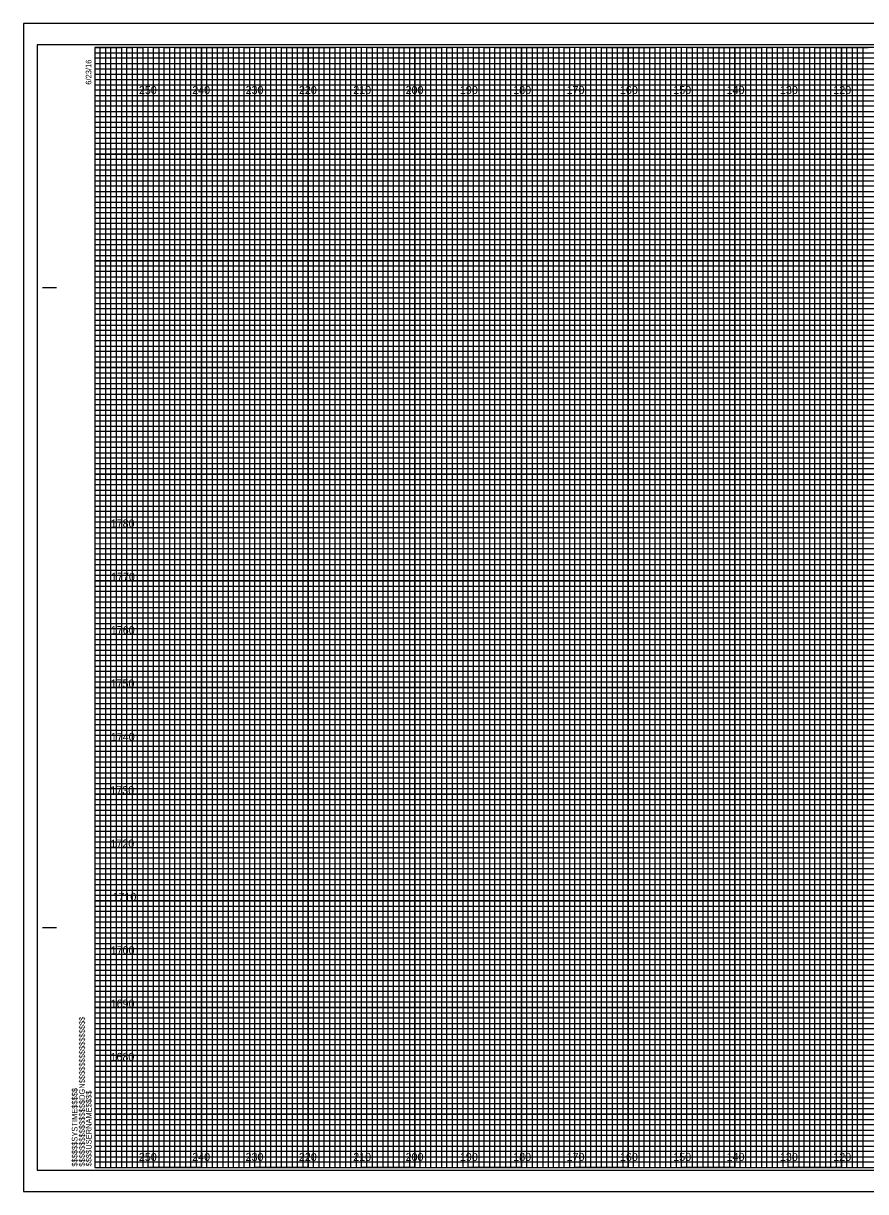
# Model space of a CAD drawing. Extents: x -13 to 1780, y -15 to 3284.
# Drawn here: x 1098.4 to 1256.3, y -11.3 to 207.7 of the extents above; entities that cross this region are included whole.
import ezdxf

# ---------------------------------------------------------------- set-up
doc = ezdxf.new("R2010")
doc.units = 0
for name, color, linetype in [('Prop Retaining Wall', 7, 'Continuous'), ('Prop SS Cut Line', 7, 'Continuous'), ('Prop SS Fill Line', 7, 'Continuous'), ('Prop SS Transition Line', 7, 'Continuous'), ('Prop XS Earthwork Shape', 7, 'Continuous'), ('Prop XS Noise Wall', 7, 'Continuous'), ('Prop XS Station Labels', 7, 'Continuous'), ('Raster_Level_0', 7, 'Continuous'), ('Scratch_Level_3', 7, 'Continuous'), ('Scratch_Level_7', 7, 'Continuous'), ('Typical Bridge Rail CELL', 7, 'Continuous')]:
    doc.layers.add(name, color=color, linetype=linetype)

msp = doc.modelspace()

# ---------------------------------------------------------------- linework, layer by layer
at = {"layer": 'Prop Retaining Wall'}
for p, q in [((1101.99, 158.2), (1104.49, 158.2)), ((1102.09, 158.2), (1104.59, 158.2)), ((1101.99, 38.2), (1104.49, 38.2)), ((1102.09, 38.2), (1104.59, 38.2)), ((1111.79, -6.8), (1111.79, -6.8)), ((1111.79, -6.8), (1111.79, -6.8)), ((1111.79, -6.8), (1111.79, -6.8)), ((1111.79, -6.8), (1111.79, -6.8)), ((1111.79, -6.8), (1111.79, -6.8)), ((1111.79, -6.8), (1111.79, -6.8)), ((1111.79, -6.8), (1111.79, -6.8))]:
    msp.add_line(p, q, dxfattribs=at)
msp.add_lwpolyline([(1431.79, 203.2), (1111.79, 203.2), (1111.79, -6.8), (1431.79, -6.8)], close=True, dxfattribs=at)
at = {"layer": 'Prop SS Cut Line'}
for points in [[(1111.79, 203.2), (1116.79, 203.2), (1116.79, -6.8), (1126.79, -6.8), (1126.79, 203.2), (1136.79, 203.2), (1136.79, -6.8), (1146.79, -6.8), (1146.79, 203.2), (1156.79, 203.2), (1156.79, -6.8), (1166.79, -6.8), (1166.79, 203.2), (1176.79, 203.2), (1176.79, -6.8), (1186.79, -6.8), (1186.79, 203.2), (1196.79, 203.2), (1196.79, -6.8), (1206.79, -6.8), (1206.79, 203.2), (1216.79, 203.2), (1216.79, -6.8), (1226.79, -6.8), (1226.79, 203.2), (1236.79, 203.2), (1236.79, -6.8), (1246.79, -6.8), (1246.79, 203.2), (1256.79, 203.2)], [(1111.79, 198.2), (1386.79, 198.2)], [(1111.79, 178.2), (1431.79, 178.2), (1431.79, 188.2), (1111.79, 188.2)], [(1111.79, 158.2), (1431.79, 158.2), (1431.79, 168.2), (1111.79, 168.2)], [(1111.79, 138.2), (1431.79, 138.2), (1431.79, 148.2), (1111.79, 148.2)], [(1111.79, 118.2), (1431.79, 118.2), (1431.79, 128.2), (1111.79, 128.2)], [(1111.79, 98.2), (1431.79, 98.2), (1431.79, 108.2), (1111.79, 108.2)], [(1111.79, 78.2), (1431.79, 78.2), (1431.79, 88.2), (1111.79, 88.2)], [(1111.79, 58.2), (1431.79, 58.2), (1431.79, 68.2), (1111.79, 68.2)], [(1111.79, 38.2), (1431.79, 38.2), (1431.79, 48.2), (1111.79, 48.2)], [(1111.79, 18.2), (1431.79, 18.2), (1431.79, 28.2), (1111.79, 28.2)], [(1111.79, -1.8), (1431.79, -1.8), (1431.79, 8.2), (1111.79, 8.2)]]:
    msp.add_lwpolyline(points, dxfattribs=at)
at = {"layer": 'Prop SS Fill Line'}
for p, q in [((1121.79, 203.2), (1111.79, 203.2)), ((1121.79, -6.8), (1121.79, 203.2)), ((1141.79, 203.2), (1131.79, 203.2)), ((1131.79, 203.2), (1131.79, -6.8)), ((1141.79, -6.8), (1141.79, 203.2)), ((1161.79, 203.2), (1151.79, 203.2)), ((1151.79, 203.2), (1151.79, -6.8)), ((1161.79, -6.8), (1161.79, 203.2)), ((1181.79, 203.2), (1171.79, 203.2)), ((1171.79, 203.2), (1171.79, -6.8)), ((1181.79, -6.8), (1181.79, 203.2)), ((1201.79, 203.2), (1191.79, 203.2)), ((1191.79, 203.2), (1191.79, -6.8)), ((1201.79, -6.8), (1201.79, 203.2)), ((1221.79, 203.2), (1211.79, 203.2)), ((1211.79, 203.2), (1211.79, -6.8)), ((1221.79, -6.8), (1221.79, 203.2)), ((1241.79, 203.2), (1231.79, 203.2)), ((1231.79, 203.2), (1231.79, -6.8)), ((1241.79, -6.8), (1241.79, 203.2)), ((1261.79, 203.2), (1251.79, 203.2)), ((1251.79, 203.2), (1251.79, -6.8)), ((1131.79, -6.8), (1121.79, -6.8)), ((1151.79, -6.8), (1141.79, -6.8)), ((1171.79, -6.8), (1161.79, -6.8)), ((1191.79, -6.8), (1181.79, -6.8)), ((1211.79, -6.8), (1201.79, -6.8)), ((1231.79, -6.8), (1221.79, -6.8)), ((1251.79, -6.8), (1241.79, -6.8))]:
    msp.add_line(p, q, dxfattribs=at)
for points in [[(1111.79, 193.2), (1431.79, 193.2), (1431.79, 183.2), (1111.79, 183.2)], [(1111.79, 173.2), (1431.79, 173.2), (1431.79, 163.2), (1111.79, 163.2)], [(1111.79, 153.2), (1431.79, 153.2), (1431.79, 143.2), (1111.79, 143.2)], [(1111.79, 133.2), (1431.79, 133.2), (1431.79, 123.2), (1111.79, 123.2)], [(1111.79, 113.2), (1431.79, 113.2), (1431.79, 103.2), (1111.79, 103.2)], [(1111.79, 93.2), (1431.79, 93.2), (1431.79, 83.2), (1111.79, 83.2)], [(1111.79, 73.2), (1431.79, 73.2), (1431.79, 63.2), (1111.79, 63.2)], [(1111.79, 53.2), (1431.79, 53.2), (1431.79, 43.2), (1111.79, 43.2)], [(1111.79, 33.2), (1431.79, 33.2), (1431.79, 23.2), (1111.79, 23.2)], [(1111.79, 13.2), (1431.79, 13.2), (1431.79, 3.2), (1111.79, 3.2)]]:
    msp.add_lwpolyline(points, dxfattribs=at)
at = {"layer": 'Prop SS Transition Line'}
for p, q in [((1111.79, 202.2), (1371.79, 202.2)), ((1371.79, 201.18), (1111.79, 201.18)), ((1111.79, 201.18), (1111.79, 200.2)), ((1111.79, 200.2), (1371.79, 200.2)), ((1371.79, 199.09), (1111.79, 199.09)), ((1111.79, 199.09), (1111.79, 197.2)), ((1111.79, 197.2), (1431.79, 197.2))]:
    msp.add_line(p, q, dxfattribs=at)
for points in [[(1111.79, 196.2), (1381.79, 196.2), (1431.79, 196.2), (1431.79, 195.2), (1111.79, 195.2)], [(1111.79, 194.2), (1431.79, 194.2), (1431.79, 192.2), (1111.79, 192.2)], [(1111.79, 191.2), (1431.79, 191.2), (1431.79, 190.2), (1111.79, 190.18)], [(1111.79, 189.2), (1431.79, 189.2), (1431.79, 187.2), (1111.79, 187.2)], [(1111.79, 186.2), (1431.79, 186.2), (1431.79, 185.2), (1111.79, 185.2)], [(1111.79, 184.2), (1431.79, 184.2), (1431.79, 182.2), (1111.79, 182.2)], [(1111.79, 181.2), (1431.79, 181.2), (1431.79, 180.2), (1111.79, 180.2)], [(1111.79, 179.2), (1431.79, 179.2), (1431.79, 177.2), (1111.79, 177.2)], [(1111.79, 176.2), (1431.79, 176.2), (1431.79, 175.2), (1111.79, 175.2)], [(1111.79, 174.2), (1431.79, 174.2), (1431.79, 172.2), (1111.79, 172.2)], [(1111.79, 171.2), (1431.79, 171.2), (1431.79, 170.2), (1111.79, 170.2)], [(1111.79, 169.2), (1431.79, 169.2), (1431.79, 167.15), (1431.79, 166.2), (1431.79, 165.2), (1111.79, 165.2)], [(1111.79, 167.2), (1431.79, 167.2), (1431.79, 166.2), (1111.79, 166.2)], [(1111.79, 164.2), (1431.79, 164.2), (1431.79, 162.2), (1111.79, 162.23)], [(1111.79, 162.23), (1431.79, 162.2), (1431.79, 161.2), (1111.79, 161.2)], [(1111.79, 160.2), (1431.79, 160.2), (1431.79, 159.2), (1111.79, 159.2)], [(1111.79, 157.2), (1431.79, 157.2), (1431.79, 156.2), (1111.79, 156.2)], [(1111.79, 155.2), (1431.79, 155.2), (1431.79, 154.2), (1111.79, 154.2)], [(1111.72, 152.09), (1431.79, 152.09), (1431.79, 151.08), (1111.72, 151.08)], [(1111.79, 150.2), (1431.79, 150.2), (1431.79, 149.2), (1111.79, 149.2)], [(1111.79, 147.2), (1431.79, 147.2), (1431.79, 146.2), (1111.79, 146.2)], [(1111.79, 145.2), (1431.79, 145.2), (1431.79, 144.2), (1111.79, 144.2)], [(1111.79, 142.2), (1431.79, 142.2), (1431.79, 141.2), (1111.79, 141.2)], [(1111.79, 140.2), (1431.79, 140.2), (1431.79, 139.2), (1111.79, 139.2)], [(1111.79, 137.2), (1431.79, 137.2), (1431.79, 136.2), (1111.79, 136.2)], [(1111.79, 135.2), (1431.79, 135.2), (1431.79, 134.2), (1111.79, 134.2)], [(1111.79, 132.2), (1431.79, 132.2), (1431.78, 131.18), (1111.79, 131.2)], [(1111.79, 130.2), (1431.79, 130.2), (1431.79, 129.2), (1111.79, 129.2)], [(1111.79, 127.2), (1431.79, 127.2), (1431.79, 126.2), (1111.79, 126.2)], [(1111.79, 125.2), (1431.79, 125.2), (1431.79, 124.2), (1111.79, 124.2)], [(1111.79, 122.2), (1431.79, 122.2), (1431.79, 121.2), (1111.79, 121.2)], [(1111.79, 120.2), (1431.79, 120.2), (1431.79, 119.2), (1111.79, 119.2)], [(1111.79, 117.2), (1431.79, 117.2), (1431.79, 116.2), (1111.79, 116.2)], [(1111.79, 115.2), (1431.79, 115.2), (1431.79, 114.2), (1111.79, 114.2)], [(1111.79, 112.2), (1431.79, 112.2), (1431.79, 111.2), (1111.79, 111.2)], [(1111.79, 110.19), (1431.86, 110.11), (1431.79, 109.2), (1111.79, 109.2)], [(1111.79, 107.2), (1431.79, 107.2), (1431.79, 106.2), (1111.79, 106.2)], [(1111.79, 105.2), (1431.79, 105.2), (1431.79, 104.2), (1111.79, 104.2)], [(1111.79, 102.2), (1431.79, 102.2), (1431.79, 101.2), (1111.79, 101.2)], [(1111.79, 100.2), (1431.79, 100.2), (1431.79, 99.2), (1111.79, 99.2)], [(1111.79, 97.2), (1431.79, 97.2), (1431.79, 96.2), (1111.79, 96.2)], [(1111.79, 95.2), (1431.79, 95.2), (1431.79, 94.2), (1111.79, 94.2)], [(1111.79, 92.2), (1431.79, 92.2), (1431.79, 91.2), (1111.79, 91.2)], [(1111.79, 90.2), (1431.79, 90.2), (1431.79, 89.2), (1111.79, 89.2)], [(1111.79, 87.2), (1431.79, 87.2), (1431.79, 86.2), (1111.79, 86.2)], [(1111.79, 85.2), (1431.79, 85.2), (1431.79, 84.2), (1111.79, 84.2)], [(1111.79, 82.2), (1431.79, 82.2), (1431.79, 81.2), (1111.79, 81.2)], [(1111.79, 80.2), (1431.79, 80.2), (1431.79, 79.2), (1111.79, 79.2)], [(1111.79, 77.2), (1431.79, 77.2), (1431.79, 76.2), (1111.79, 76.2)], [(1111.79, 75.2), (1431.79, 75.2), (1431.79, 74.2), (1111.79, 74.2)], [(1111.79, 72.2), (1431.79, 72.2), (1431.78, 71.18), (1111.79, 71.2)], [(1111.79, 70.2), (1431.79, 70.2), (1431.79, 69.2), (1111.79, 69.2)], [(1111.79, 67.2), (1431.79, 67.2), (1431.79, 66.2), (1111.79, 66.2)], [(1111.79, 65.2), (1431.79, 65.2), (1431.79, 64.2), (1111.79, 64.2)], [(1111.79, 62.2), (1431.79, 62.2), (1431.79, 61.2), (1111.79, 61.2)], [(1111.79, 60.2), (1431.79, 60.2), (1431.79, 59.2), (1111.79, 59.2)], [(1111.79, 57.2), (1431.79, 57.2), (1431.79, 56.2), (1111.79, 56.2)], [(1111.79, 55.2), (1431.79, 55.2), (1431.79, 54.2), (1111.79, 54.2)], [(1111.79, 52.2), (1431.79, 52.2), (1431.79, 51.2), (1111.79, 51.2)], [(1111.79, 50.19), (1431.86, 50.11), (1431.79, 49.2), (1111.79, 49.2)], [(1111.79, 47.2), (1431.79, 47.2), (1431.79, 46.2), (1111.79, 46.2)], [(1111.79, 45.2), (1431.79, 45.2), (1431.79, 44.2), (1111.79, 44.2)], [(1111.79, 42.2), (1431.79, 42.2), (1431.79, 41.2), (1111.79, 41.2)], [(1111.79, 40.2), (1431.79, 40.2), (1431.79, 39.2), (1111.79, 39.2)], [(1111.79, 37.2), (1431.79, 37.2), (1431.79, 36.2), (1111.79, 36.2)], [(1111.79, 35.2), (1431.79, 35.2), (1431.79, 34.2), (1111.79, 34.2)], [(1111.79, 32.2), (1431.79, 32.2), (1431.79, 31.2), (1111.79, 31.2)], [(1111.79, 30.2), (1431.79, 30.2), (1431.79, 29.2), (1111.79, 29.2)], [(1111.79, 27.2), (1431.79, 27.2), (1431.79, 26.2), (1111.79, 26.2)], [(1111.79, 25.2), (1431.79, 25.2), (1431.79, 24.2), (1111.79, 24.2)], [(1111.79, 22.2), (1431.79, 22.2), (1431.79, 21.2), (1111.79, 21.2)], [(1111.79, 20.2), (1431.79, 20.2), (1431.79, 19.2), (1111.79, 19.2)], [(1111.79, 17.2), (1431.79, 17.2), (1431.79, 16.2), (1111.79, 16.2)], [(1111.79, 15.2), (1431.79, 15.2), (1431.79, 14.2), (1111.79, 14.2)], [(1111.79, 12.2), (1431.79, 12.2), (1431.79, 11.2), (1111.79, 11.2)], [(1111.79, 10.2), (1431.79, 10.2), (1431.79, 9.2), (1111.79, 9.2)], [(1111.79, 7.2), (1431.79, 7.2), (1431.79, 6.2), (1111.79, 6.2)], [(1111.79, 5.2), (1431.79, 5.2), (1431.79, 4.2), (1111.79, 4.2)], [(1111.79, 2.2), (1431.79, 2.2), (1431.79, 1.2), (1111.79, 1.2)], [(1111.79, 0.2), (1431.79, 0.2), (1431.79, -0.8), (1111.79, -0.8)], [(1111.79, -2.8), (1431.79, -2.8), (1431.79, -3.8), (1111.79, -3.8)], [(1111.79, -4.8), (1431.79, -4.8), (1431.79, -5.8), (1111.79, -5.8)]]:
    msp.add_lwpolyline(points, dxfattribs=at)
at = {"layer": 'Prop XS Earthwork Shape'}
msp.add_lwpolyline([(1098.39, -11.3), (1435.09, -11.3), (1435.09, 207.7), (1098.39, 207.7)], close=True, dxfattribs=at)
at = {"layer": 'Prop XS Noise Wall'}
for p, q in [((1121.79, -6.8), (1121.79, 203.2)), ((1131.79, -6.8), (1131.79, 203.2)), ((1141.79, -6.8), (1141.79, 203.2)), ((1151.79, -6.8), (1151.79, 203.2)), ((1161.79, -6.8), (1161.79, 203.2)), ((1171.79, -6.8), (1171.79, 203.2)), ((1181.79, -6.8), (1181.79, 203.2)), ((1191.79, -6.8), (1191.79, 203.2)), ((1201.79, -6.8), (1201.79, 203.2)), ((1211.79, -6.8), (1211.79, 203.2)), ((1221.79, -6.8), (1221.79, 203.2)), ((1231.79, -6.8), (1231.79, 203.2)), ((1241.79, -6.8), (1241.79, 203.2)), ((1251.79, -6.8), (1251.79, 203.2)), ((1111.79, 193.2), (1431.79, 193.2)), ((1111.79, 183.2), (1431.79, 183.2)), ((1111.79, 173.2), (1431.79, 173.2)), ((1111.79, 163.2), (1431.79, 163.2)), ((1111.79, 153.2), (1431.79, 153.2)), ((1111.79, 143.2), (1431.79, 143.2)), ((1111.79, 133.2), (1431.79, 133.2)), ((1111.79, 123.2), (1431.79, 123.2)), ((1111.79, 113.2), (1431.79, 113.2)), ((1111.79, 103.2), (1431.79, 103.2)), ((1111.79, 93.2), (1431.79, 93.2)), ((1111.79, 83.2), (1431.79, 83.2)), ((1111.79, 73.2), (1431.79, 73.2)), ((1111.79, 63.2), (1431.79, 63.2)), ((1111.79, 53.2), (1431.79, 53.2)), ((1111.79, 43.2), (1431.79, 43.2)), ((1111.79, 33.2), (1431.79, 33.2)), ((1111.79, 23.2), (1431.79, 23.2)), ((1111.79, 13.2), (1431.79, 13.2)), ((1111.79, 3.2), (1431.79, 3.2))]:
    msp.add_line(p, q, dxfattribs=at)
at = {"layer": 'Prop XS Station Labels'}
for p, q in [((1435.09, 207.7), (1098.39, 207.7)), ((1098.39, 207.7), (1098.39, -11.3)), ((1098.39, -11.3), (1435.09, -11.3))]:
    msp.add_line(p, q, dxfattribs=at)
at = {"layer": 'Scratch_Level_7'}
msp.add_lwpolyline([(1100.99, -7.3), (1434.19, -7.3), (1434.19, 203.7), (1100.99, 203.7)], close=True, dxfattribs=at)
at = {"layer": 'Typical Bridge Rail CELL'}
for points in [[(1111.79, -6.8), (1112.79, -6.8), (1112.79, 203.2), (1113.79, 203.2), (1113.79, -6.8)], [(1113.79, -6.8), (1114.79, -6.8), (1114.79, 203.2), (1115.79, 203.2), (1115.79, -6.8)], [(1116.79, -6.8), (1117.79, -6.8), (1117.79, 203.2), (1118.79, 203.2), (1118.79, -6.8)], [(1118.79, -6.8), (1119.79, -6.8), (1119.79, 203.2), (1120.79, 203.2), (1120.79, -6.8)], [(1121.79, -6.8), (1122.79, -6.8), (1122.79, 203.2), (1123.79, 203.2), (1123.79, -6.8)], [(1123.79, -6.8), (1124.79, -6.8), (1124.79, 203.2), (1125.79, 203.2), (1125.79, -6.8)], [(1126.79, -6.8), (1127.79, -6.8), (1127.79, 203.2), (1128.79, 203.2), (1128.79, -6.8)], [(1128.79, -6.8), (1129.79, -6.8), (1129.79, 203.2), (1130.79, 203.2), (1130.79, -6.8)], [(1131.79, -6.8), (1132.79, -6.8), (1132.79, 203.2), (1133.79, 203.2), (1133.79, -6.8)], [(1133.79, -6.8), (1134.79, -6.8), (1134.79, 203.2), (1135.79, 203.2), (1135.79, -6.8)], [(1136.79, -6.8), (1137.79, -6.8), (1137.79, 203.2), (1138.79, 203.2), (1138.79, -6.8)], [(1138.79, -6.8), (1139.79, -6.8), (1139.79, 203.2), (1140.79, 203.2), (1140.79, -6.8)], [(1141.79, -6.8), (1142.79, -6.8), (1142.79, 203.2), (1143.79, 203.2), (1143.79, -6.8)], [(1143.79, -6.8), (1144.79, -6.8), (1144.79, 203.2), (1145.79, 203.2), (1145.79, -6.8)], [(1146.79, -6.8), (1147.79, -6.8), (1147.79, 203.2), (1148.79, 203.2), (1148.79, -6.8)], [(1148.79, -6.8), (1149.79, -6.8), (1149.79, 203.2), (1150.79, 203.2), (1150.79, -6.8)], [(1151.79, -6.8), (1152.79, -6.8), (1152.79, 203.2), (1153.79, 203.2), (1153.79, -6.8)], [(1153.79, -6.8), (1154.79, -6.8), (1154.79, 203.2), (1155.79, 203.2), (1155.79, -6.8)], [(1156.79, -6.8), (1157.79, -6.8), (1157.79, 203.2), (1158.79, 203.2), (1158.79, -6.8)], [(1158.79, -6.8), (1159.79, -6.8), (1159.79, 203.2), (1160.79, 203.2), (1160.79, -6.8)], [(1161.79, -6.8), (1162.79, -6.8), (1162.79, 203.2), (1163.79, 203.2), (1163.79, -6.8)], [(1163.79, -6.8), (1164.79, -6.8), (1164.79, 203.2), (1165.79, 203.2), (1165.79, -6.8)], [(1166.79, -6.8), (1167.79, -6.8), (1167.79, 203.2), (1168.79, 203.2), (1168.79, -6.8)], [(1168.79, -6.8), (1169.79, -6.8), (1169.79, 203.2), (1170.79, 203.2), (1170.79, -6.8)], [(1171.79, -6.8), (1172.79, -6.8), (1172.79, 203.2), (1173.79, 203.2), (1173.79, -6.8)], [(1173.79, -6.8), (1174.79, -6.8), (1174.79, 203.2), (1175.79, 203.2), (1175.79, -6.8)], [(1176.79, -6.8), (1177.79, -6.8), (1177.79, 203.2), (1178.79, 203.2), (1178.79, -6.8)], [(1178.79, -6.8), (1179.79, -6.8), (1179.79, 203.2), (1180.79, 203.2), (1180.79, -6.8)], [(1181.79, -6.8), (1182.79, -6.8), (1182.79, 203.2), (1183.79, 203.2), (1183.79, -6.8)], [(1183.79, -6.8), (1184.79, -6.8), (1184.79, 203.2), (1185.79, 203.2), (1185.79, -6.8)], [(1186.79, -6.8), (1187.79, -6.8), (1187.79, 203.2), (1188.79, 203.2), (1188.79, -6.8)], [(1188.79, -6.8), (1189.79, -6.8), (1189.79, 203.2), (1190.79, 203.2), (1190.79, -6.8)], [(1191.79, -6.8), (1192.79, -6.8), (1192.79, 203.2), (1193.79, 203.2), (1193.79, -6.8)], [(1193.79, -6.8), (1194.79, -6.8), (1194.79, 203.2), (1195.79, 203.2), (1195.79, -6.8)], [(1196.79, -6.8), (1197.79, -6.8), (1197.79, 203.2), (1198.79, 203.2), (1198.79, -6.8)], [(1198.79, -6.8), (1199.79, -6.8), (1199.79, 203.2), (1200.79, 203.2), (1200.79, -6.8)], [(1201.79, -6.8), (1202.79, -6.8), (1202.79, 203.2), (1203.79, 203.2), (1203.79, -6.8)], [(1203.79, -6.8), (1204.79, -6.8), (1204.79, 203.2), (1205.79, 203.2), (1205.79, -6.8)], [(1206.79, -6.8), (1207.79, -6.8), (1207.79, 203.2), (1208.79, 203.2), (1208.79, -6.8)], [(1208.79, -6.8), (1209.79, -6.8), (1209.79, 203.2), (1210.79, 203.2), (1210.79, -6.8)], [(1211.79, -6.8), (1212.79, -6.8), (1212.79, 203.2), (1213.79, 203.2), (1213.79, -6.8)], [(1213.79, -6.8), (1214.79, -6.8), (1214.79, 203.2), (1215.79, 203.2), (1215.79, -6.8)], [(1216.79, -6.8), (1217.79, -6.8), (1217.79, 203.2), (1218.79, 203.2), (1218.79, -6.8)], [(1218.79, -6.8), (1219.79, -6.8), (1219.79, 203.2), (1220.79, 203.2), (1220.79, -6.8)], [(1221.79, -6.8), (1222.79, -6.8), (1222.79, 203.2), (1223.79, 203.2), (1223.79, -6.8)], [(1223.79, -6.8), (1224.79, -6.8), (1224.79, 203.2), (1225.79, 203.2), (1225.79, -6.8)], [(1226.79, -6.8), (1227.79, -6.8), (1227.79, 203.2), (1228.79, 203.2), (1228.79, -6.8)], [(1228.79, -6.8), (1229.79, -6.8), (1229.79, 203.2), (1230.79, 203.2), (1230.79, -6.8)], [(1231.79, -6.8), (1232.79, -6.8), (1232.79, 203.2), (1233.79, 203.2), (1233.79, -6.8)], [(1233.79, -6.8), (1234.79, -6.8), (1234.79, 203.2), (1235.79, 203.2), (1235.79, -6.8)], [(1236.79, -6.8), (1237.79, -6.8), (1237.79, 203.2), (1238.79, 203.2), (1238.79, -6.8)], [(1238.79, -6.8), (1239.79, -6.8), (1239.79, 203.2), (1240.79, 203.2), (1240.79, -6.8)], [(1241.79, -6.8), (1242.79, -6.8), (1242.79, 203.2), (1243.79, 203.2), (1243.79, -6.8)], [(1243.79, -6.8), (1244.79, -6.8), (1244.79, 203.2), (1245.79, 203.2), (1245.79, -6.8)], [(1246.79, -6.8), (1247.79, -6.8), (1247.79, 203.2), (1248.79, 203.2), (1248.79, -6.8)], [(1248.79, -6.8), (1249.79, -6.8), (1249.79, 203.2), (1250.79, 203.2), (1250.79, -6.8)], [(1251.79, -6.8), (1252.79, -6.8), (1252.79, 203.2), (1253.79, 203.2), (1253.79, -6.8)], [(1253.79, -6.8), (1254.79, -6.8), (1254.79, 203.2), (1255.79, 203.2), (1255.79, -6.8)]]:
    msp.add_lwpolyline(points, dxfattribs=at)

# ---------------------------------------------------------------- texts
at = {"layer": 'Prop Retaining Wall'}
for s, p in [('6/23/16', (1111.14, 196.2)), ('$$$$$$$$$$$$$$$$DGN$$$$$$$$$$$$$$$$', (1109.91, -6.62)), ('$$$$$$SYSTIME$$$$$', (1108.53, -6.62)), ('$$$$USERNAME$$$$', (1111.17, -6.57))]:
    msp.add_text(s, height=1.05, rotation=90, dxfattribs=at).set_placement(p)
at = {"layer": 'Raster_Level_0'}
for s, p in [('250', (1120.05, 194.45)), ('240', (1130.05, 194.45)), ('230', (1140.05, 194.45)), ('220', (1150.05, 194.45)), ('210', (1160.23, 194.45)), ('200', (1170.05, 194.45)), ('190', (1180.23, 194.45)), ('180', (1190.23, 194.45)), ('170', (1200.23, 194.45)), ('160', (1210.23, 194.45)), ('150', (1220.23, 194.45)), ('140', (1230.23, 194.45)), ('130', (1240.23, 194.45)), ('120', (1250.23, 194.45)), ('250', (1120.05, -5.55)), ('240', (1130.05, -5.55)), ('230', (1140.05, -5.55)), ('220', (1150.05, -5.55)), ('210', (1160.23, -5.55)), ('200', (1170.05, -5.55)), ('190', (1180.23, -5.55)), ('180', (1190.23, -5.55)), ('170', (1200.23, -5.55)), ('160', (1210.23, -5.55)), ('150', (1220.23, -5.55)), ('140', (1230.23, -5.55)), ('130', (1240.23, -5.55)), ('120', (1250.23, -5.55))]:
    msp.add_text(s, height=1.5, dxfattribs=at).set_placement(p)
at = {"layer": 'Scratch_Level_3'}
for s, p in [('1780', (1114.77, 113.2)), ('1770', (1114.83, 103.2)), ('1760', (1114.79, 93.2)), ('1750', (1114.75, 83.2)), ('1740', (1114.79, 73.2)), ('1730', (1114.71, 63.2)), ('1720', (1114.72, 53.2)), ('1710', (1115.1, 43.2)), ('1700', (1114.77, 33.2)), ('1690', (1114.76, 23.2)), ('1680', (1114.73, 13.2))]:
    msp.add_text(s, height=1.5, dxfattribs=at).set_placement(p)

doc.saveas('drawing.dxf')
